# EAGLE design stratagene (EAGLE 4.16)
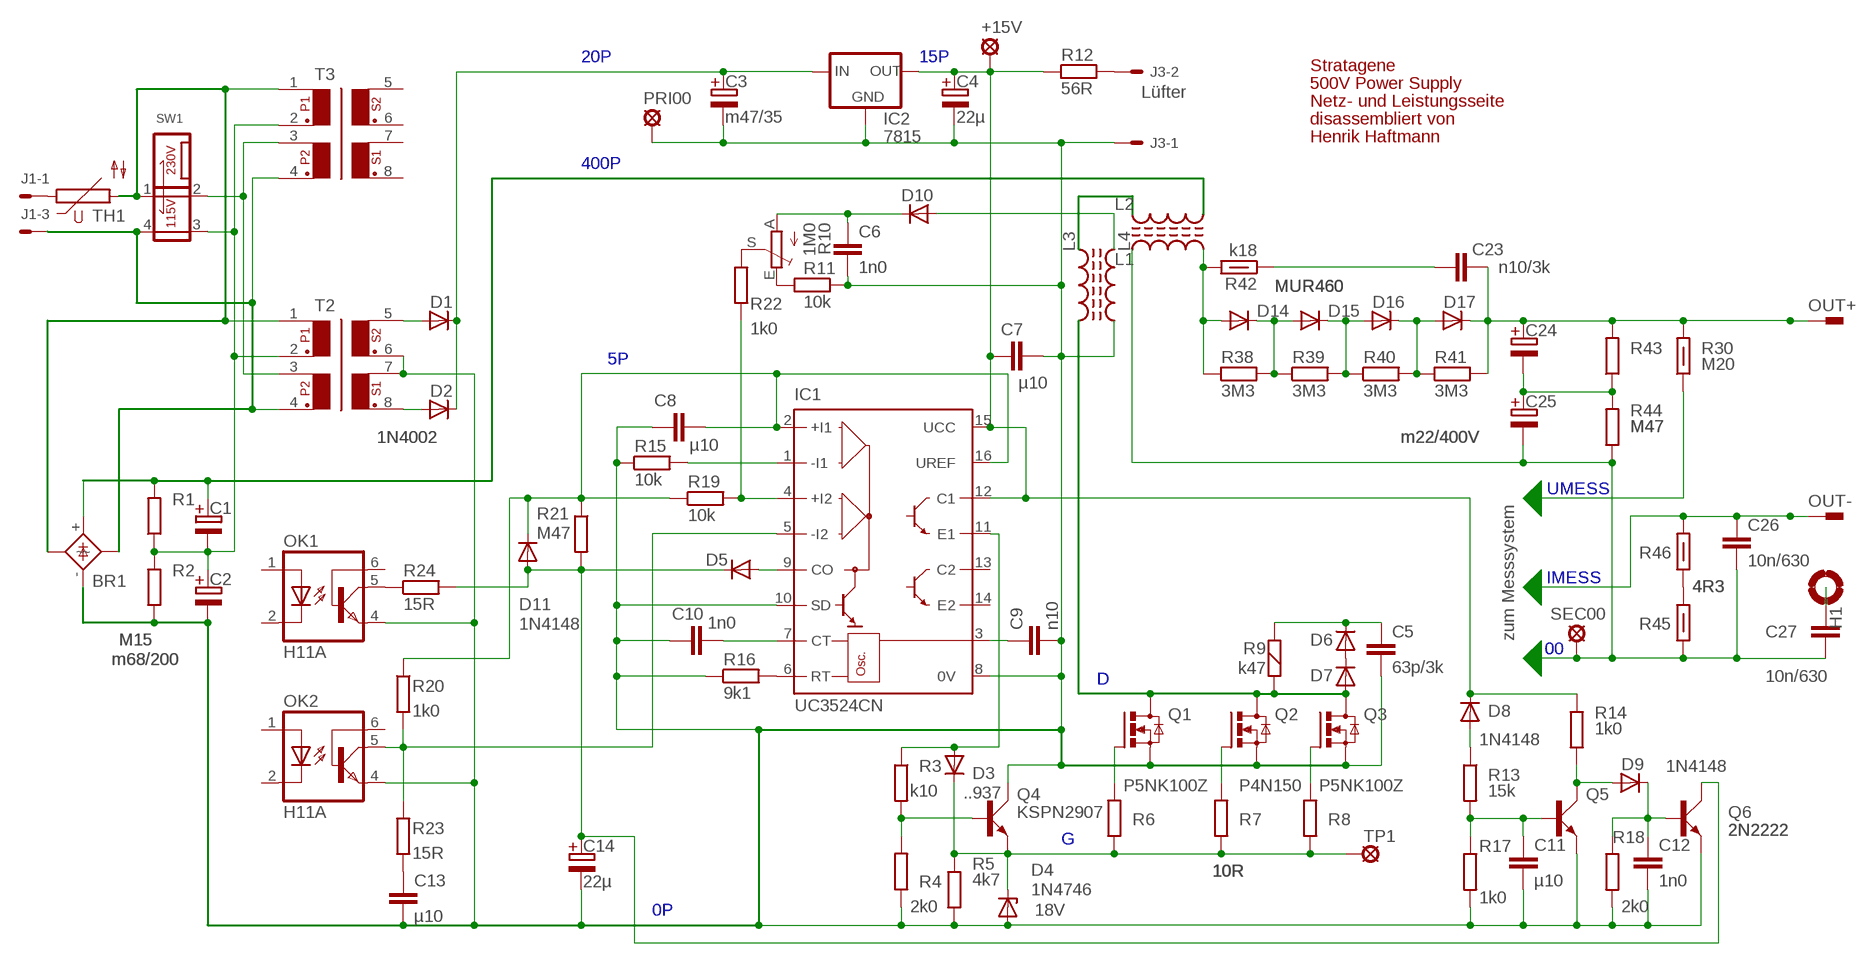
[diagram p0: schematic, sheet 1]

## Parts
+15V  LSP10  [LSP10]
BR1  DB  [GBPC1]
C1  m68/200  E04-26  [E04-26]
C2  m68/200  E04-26  [E04-26]
C3  m47/35  E02-10  [E02-10]
C4  22µ  E01-5  [E01-5]
C5  63p/3k  C02  [C02]
C6  1n0  C02  [C02]
C7  µ10  C02  [C02]
C8  µ10  C02  [C02]
C9  n10  C02  [C02]
C10  1n0  C02  [C02]
C11  µ10  C02  [C02]
C12  1n0  C02  [C02]
C13  µ10  C02  [C02]
C14  22µ  E01-5  [E01-5]
C23  n10/3k  C02  [C02]
C24  m22/400V  E04-26  [E04-26]
C25  m22/400V  E04-26  [E04-26]
C26  10n/630  C04  [C04]
C27  10n/630  C04  [C04]
D1  1N4002  D05  [D05]
D2  1N4002  D05  [D05]
D3  ..937  D05  [D05]
D4  1N4746  DZ05  [D05]
D5  D05  [D05]
D6  D05  [D05]
D7  D05  [D05]
D8  1N4148  D05  [D05]
D9  1N4148  D05  [D05]
D10  D05  [D05]
D11  1N4148  D05  [D05]
D14  MUR460  D07  [D07]
D15  MUR460  D07  [D07]
D16  MUR460  D07  [D07]
D17  MUR460  D07  [D07]
H1  MOUNT-PAD-ROUND4.1  [4,1-PAD]
IC1  UC3524CN  [DIL16]
IC2  7815  78XXS  [78XXS]
J1  22-27-2031-03  [6410-03]
J3  22-27-2021-02  [6410-02]
L1  L02  [R02]
L2  L04  [R04]
L3  L05  [R05]
L4  L05  [R05]
OK1  H11A  CNY17  [DIL06]
OK2  H11A  CNY17  [DIL06]
OUT+  PIN2F061.040  [F061.040]
OUT-  PIN2F061.040  [F061.040]
PRI00  LSP10  [LSP10]
Q1  P5NK100Z  NMOS220  [TO220V]
Q2  P4N150  NMOS220  [TO220V]
Q3  P5NK100Z  NMOS220  [TO220V]
Q4  KSPN2907  NPN92EBC  [TO92V]
Q5  2N2222  NPN92EBC  [TO92V]
Q6  2N2222  NPN92EBC  [TO92V]
R1  M15  R06  [R06]
R2  M15  R06  [R06]
R3  k10  R05  [R05]
R4  2k0  R05  [R05]
R5  4k7  R05  [R05]
R6  10R  R05  [R05]
R7  10R  R05  [R05]
R8  10R  R05  [R05]
R9  k47  R208  [R208]
R10  1M0  RAS64W  [S64W]
R11  10k  R05  [R05]
R12  56R  R05  [R05]
R13  15k  R05  [R05]
R14  1k0  R05  [R05]
R15  10k  R05  [R05]
R16  9k1  R05  [R05]
R17  1k0  R05  [R05]
R18  2k0  R05  [R05]
R19  10k  R05  [R05]
R20  1k0  R05  [R05]
R21  M47  R05  [R05]
R22  1k0  R05  [R05]
R23  15R  R05  [R05]
R24  15R  R05  [R05]
R30  M20  R08  [R08]
R38  3M3  R06  [R06]
R39  3M3  R06  [R06]
R40  3M3  R06  [R06]
R41  3M3  R06  [R06]
R42  k18  R08  [R08]
R43  M47  R06  [R06]
R44  M47  R06  [R06]
R45  4R3  R08  [R08]
R46  4R3  R08  [R08]
SEC00  LSP10  [LSP10]
SW1  SWA  [SWA]
T2  T2-2  [T42X34]
T3  T2-2  [T42X34]
TH1  P592  [P592]
TP1  LSP10  [LSP10]

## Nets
00: C25.- C26.2 C27.2 L1.1 R44.1 R45.1 SEC00.MP
0P: BR1.- C2.- C3.- C4.- C5.2 C6.2 C7.2 C8.2 C9.2 C10.2 C11.1 C12.2 C13.2 C14.- D4.1(A) IC1.8(0V) IC1.10(SD) IC2.GND J3.1 L4.2 OK1.4(EMI) OK2.4(EMI) PRI00.MP Q1.3(S) Q2.3(S) Q3.3(S) Q4.3(C) Q5.1(E) Q6.1(E) R2.1 R4.1 R5.2 R11.1 R15.1 R16.1 R17.2 R18.2 T2.6 T2.7
5P: C8.1 D11.2(K) IC1.2(+I1) IC1.16(UREF) R19.1 R20.1 R21.1
15P: +15V.MP C4.+ C7.1 D8.2(K) IC1.12(C1) IC1.15(UCC) IC2.OUT R12.1 R14.1
20P: C3.+ D1.2(K) D2.2(K) IC2.IN
400P: BR1.+ C1.+ L2.2 R1.2
D: D7.1(A) L3.2 Q1.2(D) Q2.2(D) Q3.2(D) R9.1
G: D3.2(K) D4.2(K) Q4.1(E) R5.1 R6.1 R7.1 R8.1 TP1.MP
IMESS: C26.1 OUT-.A1 OUT-.A2(1.1) R46.2
N$1: IC1.1(-I1) R15.2
N$2: C11.2 Q5.2(B) R13.2 R17.1
N$3: IC1.4(+I2) R19.2 R22.2
N$4: C14.+ D5.2(K) D11.1(A) Q6.3(C) R21.2 R24.2
N$5: J1.1 TH1.1
N$6: D14.1(A) L1.2 R38.1 R42.2
N$7: L2.1 L3.1
N$8: C23.1 R42.1
N$9: D14.2(K) D15.1(A) R38.2 R39.1
N$10: R45.2 R46.1
N$11: C24.- C25.+ R43.1 R44.2
N$14: D15.2(K) D16.1(A) R39.2 R40.1
N$15: D16.2(K) D17.1(A) R40.2 R41.1
N$16: C23.2 C24.+ D17.2(K) OUT+.A1 OUT+.A2(1.1) R30.2 R41.2 R43.2
N$19: Q1.1(G) R6.2
N$20: Q2.1(G) R7.2
N$21: Q3.1(G) R8.2
N$24: D5.1(A) IC1.9(CO)
N$25: C5.1 D6.2(K) R9.2
N$26: D6.1(A) D7.2(K)
N$27: J3.2 R12.2
N$28: D1.1(A) T2.5
N$29: D2.1(A) T2.8
N$30: C9.1 IC1.3(OSCOUT)
N$31: C10.1 IC1.7(CT)
N$32: Q4.2(B) R3.2 R4.2
N$34: D3.1(A) IC1.11(E1) R3.1
N$35: C27.1 H1.B4,1(MOUNT)
N$37: IC1.6(RT) R16.2
N$38: BR1.~@2(~) SW1.1 T2.1 T3.1 TH1.2
N$39: C1.- C2.+ R1.1 R2.2 SW1.3 T2.2 T3.2
N$40: SW1.2 T2.3 T3.3
N$41: BR1.~@1(~) J1.3 SW1.4 T2.4 T3.4
N$42: IC1.5(-I2) OK2.5(COL) R20.2 R23.1
N$44: D9.1(A) Q5.3(C) R14.2
N$45: D8.1(A) R13.1
N$46: D10.1(A) L4.1
N$47: C6.1 D10.2(K) R10.A
N$48: R10.S R22.1
N$49: R10.E R11.2
N$50: C12.1 D9.2(K) Q6.2(B) R18.1
N$51: OK1.5(COL) R24.1
N$52: C13.1 R23.2
UMESS: R30.1
Unconnected: IC1.13(C2) IC1.14(E2) J1.2 OK1.1(A) OK1.2(C) OK1.6(BAS) OK2.1(A) OK2.2(C) OK2.6(BAS) T3.5 T3.6 T3.7 T3.8

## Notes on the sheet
- Stratagene
- 500V Power Supply
- Lüfter
- Netz- und Leistungsseite
- disassembliert von
- Henrik Haftmann
- zum Messsystem
- 18V

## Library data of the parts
+15V PRI00 SEC00 TP1 = solpad:LSP10: SOLDER PAD
BR1 = stratagene:DB: Gleichrichterbrücke
C1-C4 C14 C24 C25 = stratagene:E: Elektrolytkondensator, gepolt
C5-C13 C23 C26 C27 = stratagene:C: Kondensator
D1-D3 D5-D11 D14-D17 = stratagene:D: Diode
D4 = stratagene:DZ: Z-Diode
H1 = holes:MOUNT-PAD-ROUND: MOUNTING PAD, round
IC1 = stratagene:UC3524: SWITCHMODE Pulse Width Modulation Control Circuit NCV494B http://onsemi.com tl494-d.pdf
IC2 = v-reg:78XXS: VOLTAGE REGULATOR
J1 = con-molex:22-?-03: CONNECTOR wire to board 2.54 mm (.1 inch) pitch header
J3 = con-molex:22-?-02: CONNECTOR
L1-L4 = stratagene:L: Spule, Drossel
OK1 OK2 = optocoupler:CNY17: SIEMENS OPTO COUPLER
OUT+ OUT- = con-faston:PIN2: Flachstecker Typ tyco/Electronics/AMP
Q1-Q3 = stratagene:NMOS: n-Kanal-MOSFET mit Bulkdiode
Q4-Q6 = stratagene:NPN: npn-Transistor Anschlussfolge CEB nur für SF225, SF240, SF245! Anschlussfolge ECB für japanische 2SC945 und ähnliche Anschlussfolge BEC für alle SMD-Transistoren
R1-R9 R11-R24 R30 R38-R46 = stratagene:R: Widerstand
R10 = stratagene:RA: Einstellpotenziometer dreipolig
SW1 = stratagene:SWA: Spannungsumschalter für Trafo Auch für Schaltnetzteile
T2 T3 = stratagene:T2-2: Netztrafo
TH1 = varistor:P592: VARISTOR

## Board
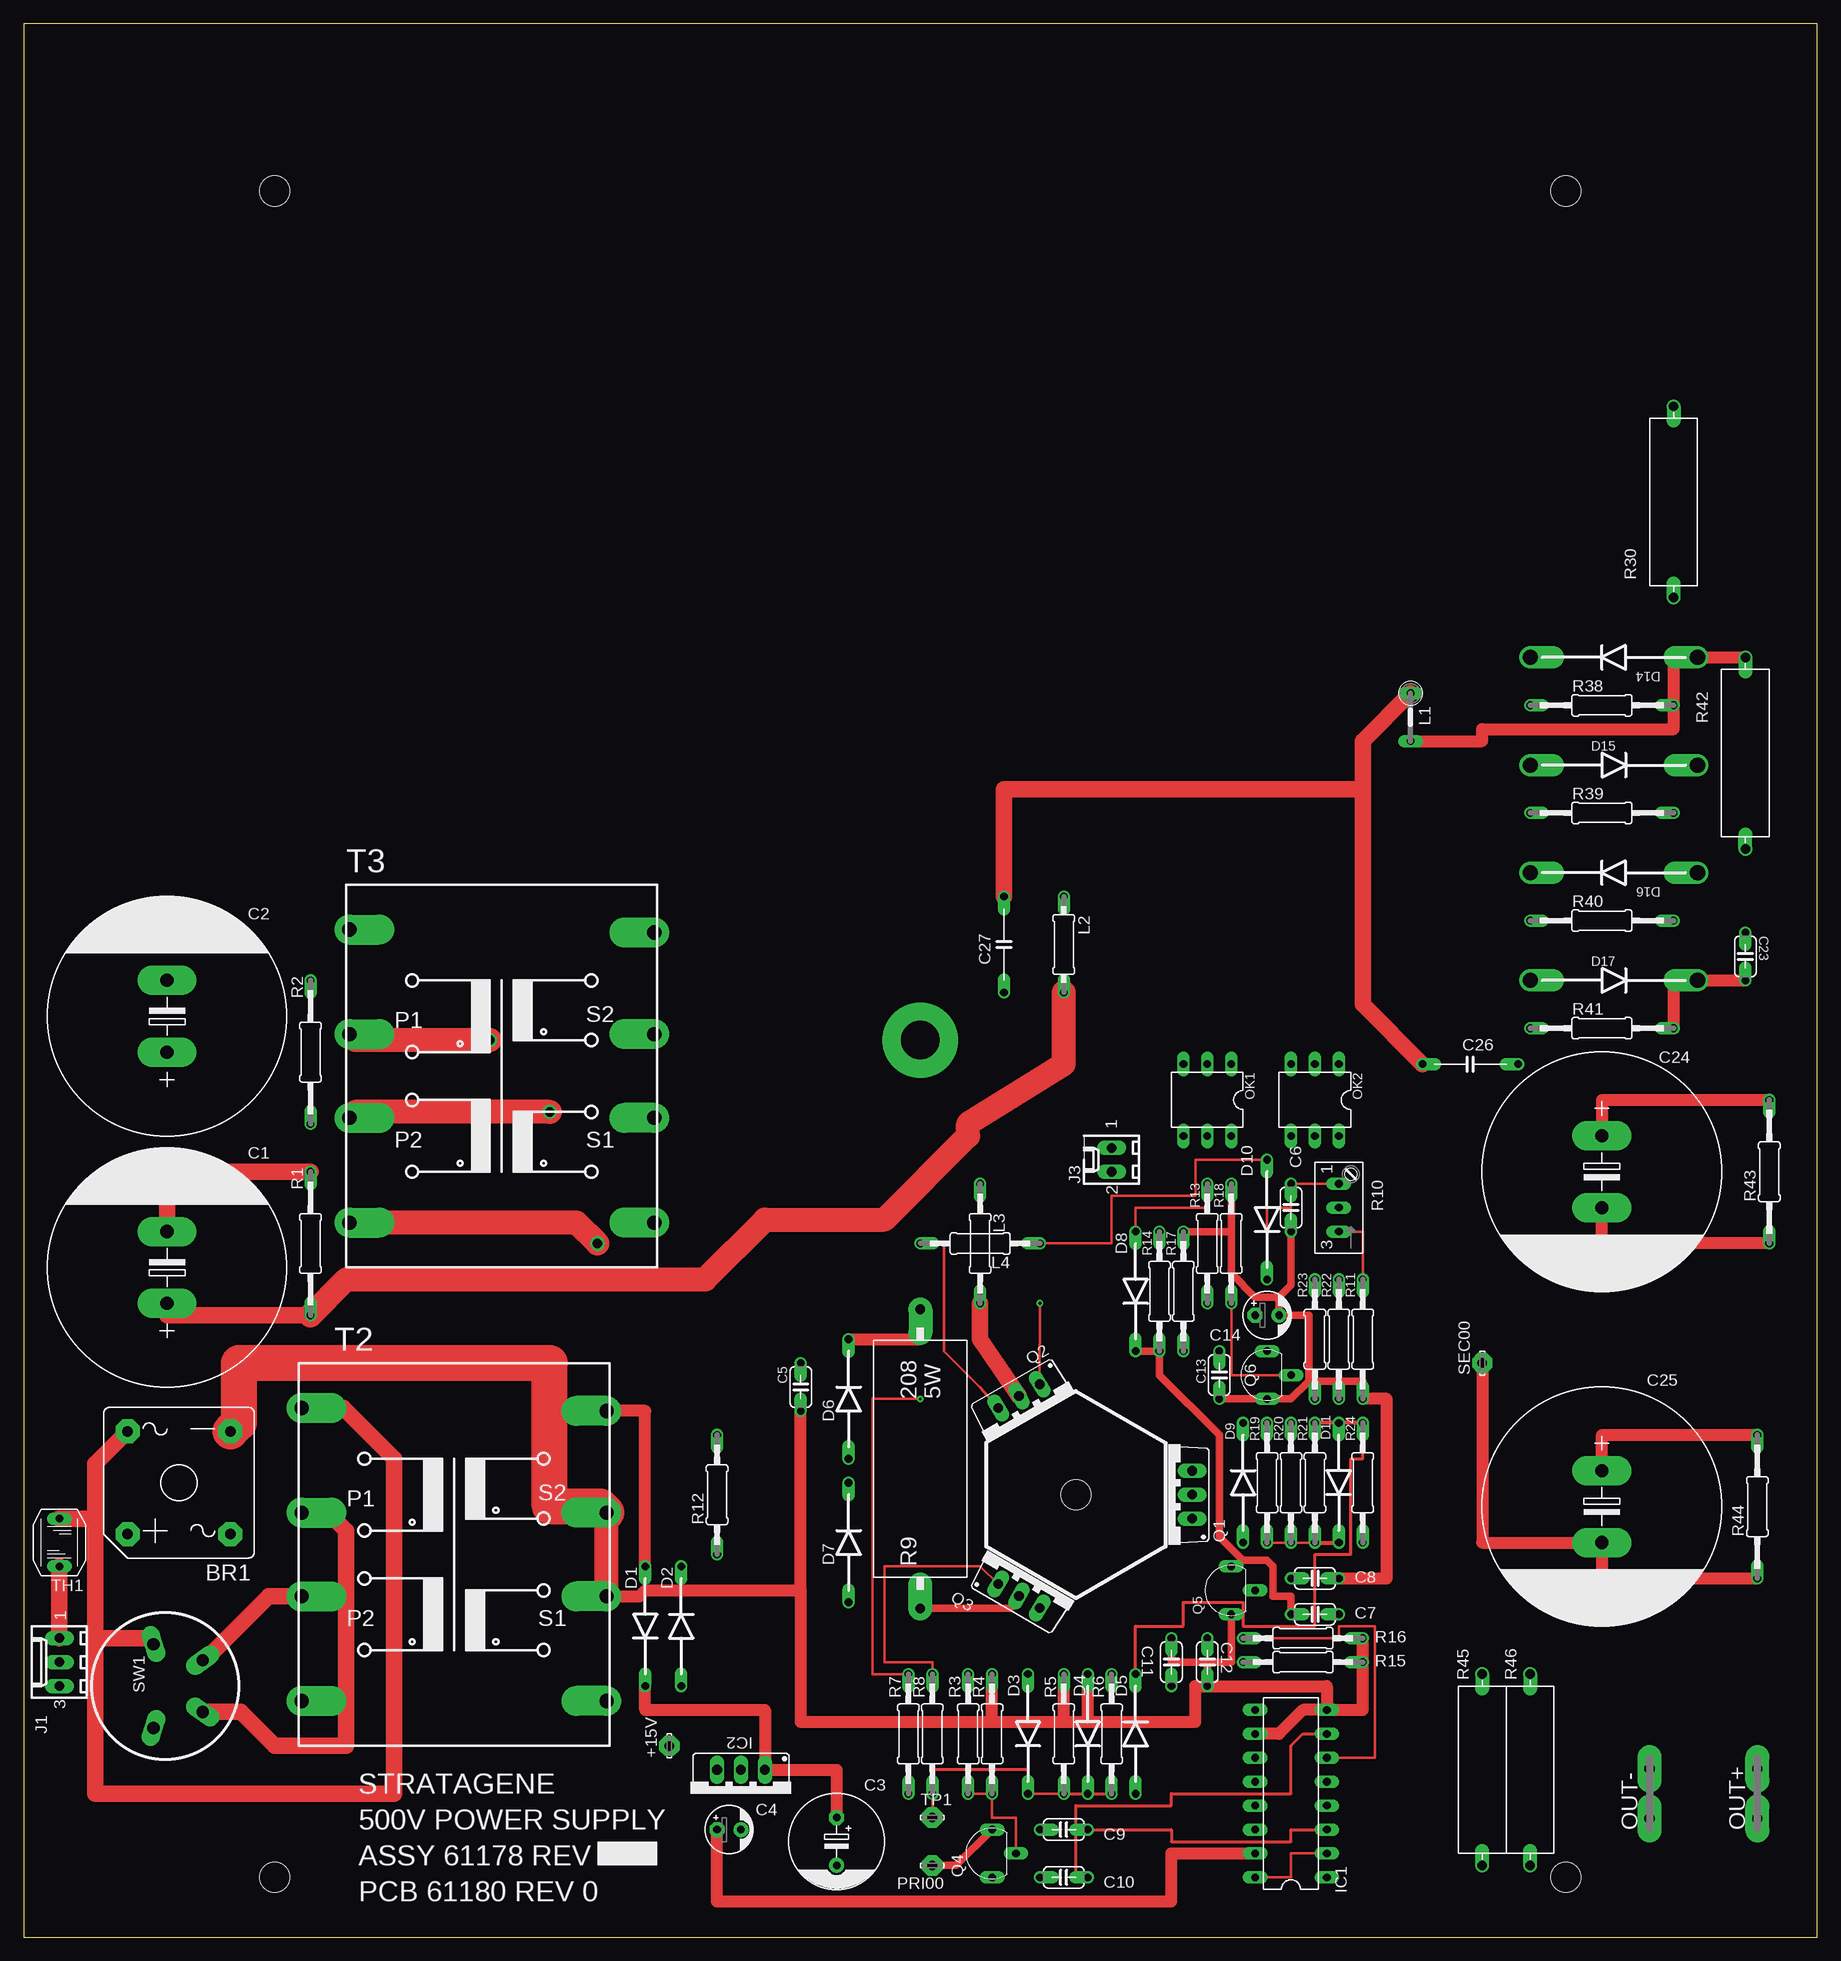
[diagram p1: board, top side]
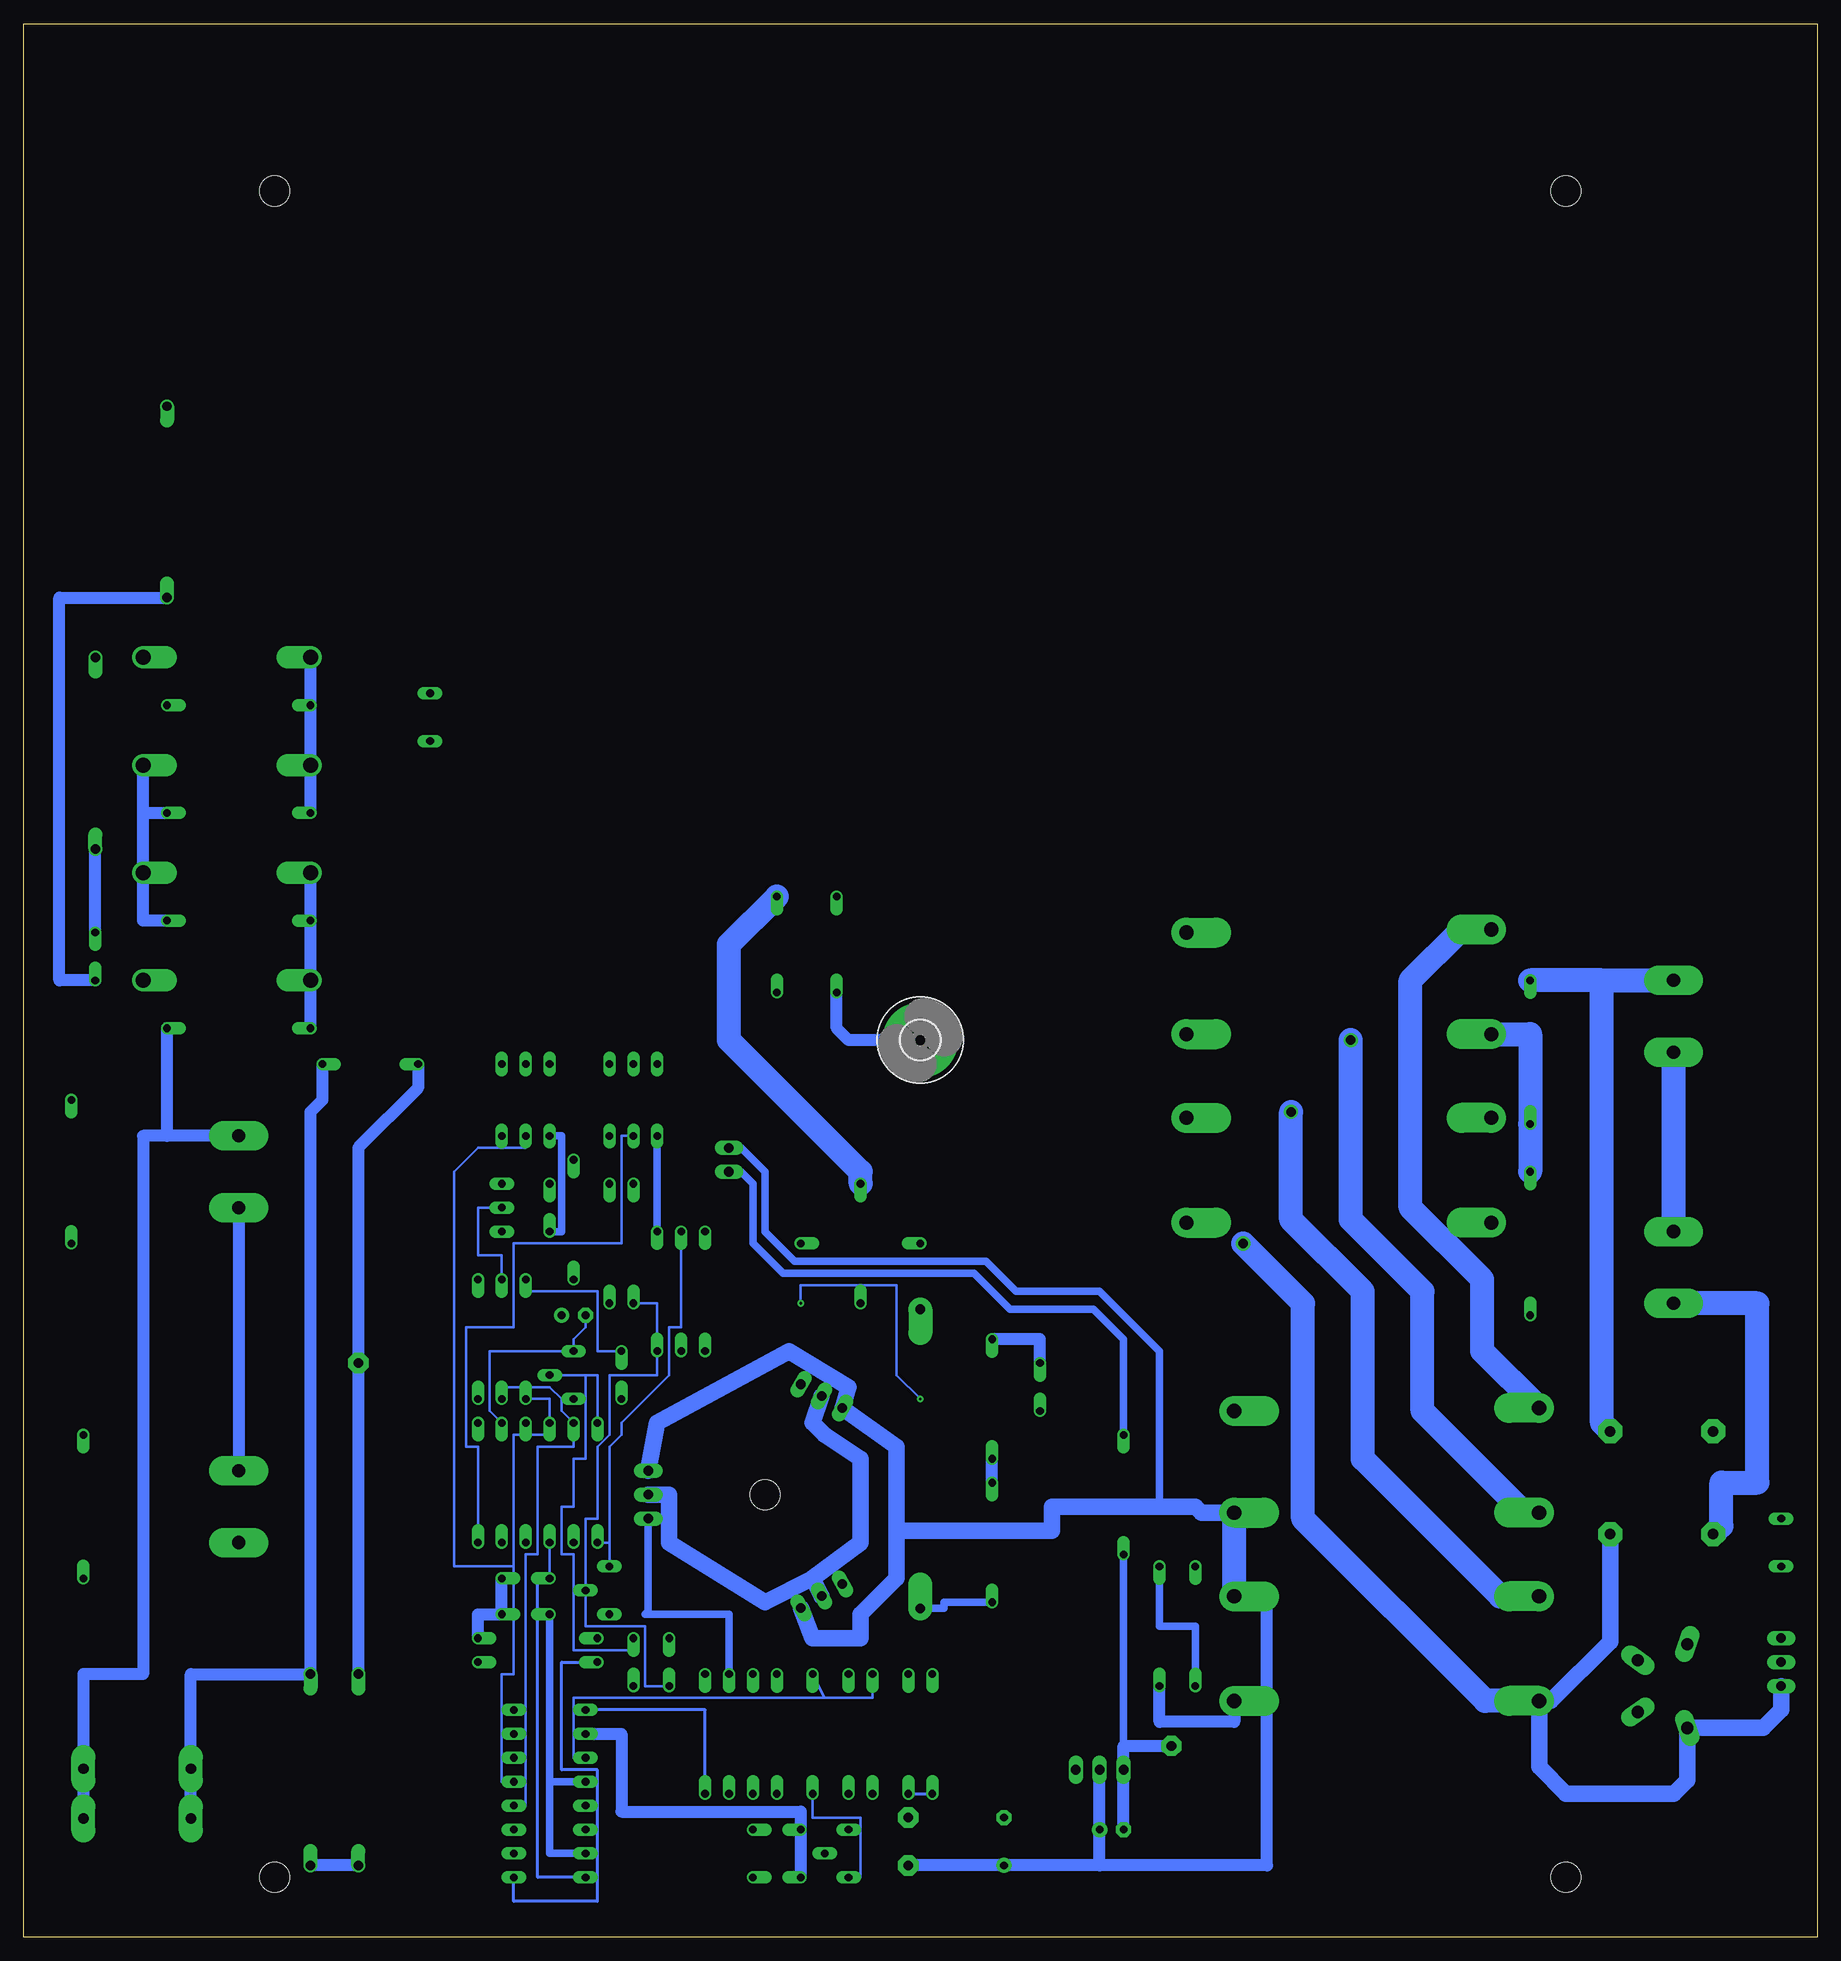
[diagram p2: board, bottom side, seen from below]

Size 190.5 x 203.2 mm. Coordinates in mm from the lower left corner, seen from the top.
Outline: 0,0 190.5,0 190.5,203.2 0,203.2 0,0
Copper layers (1+16): Top 0.035mm / dielectric 1.5mm / Bottom 0.035mm
Design rules "default": minimum track width 0.15mm, minimum drill 0.3mm, track to track 8mil, track to pad 8mil, pad to pad 8mil, via to via 8mil, smd to smd 8mil, copper to edge 40mil, drill to drill 8mil, minimum pad ring 10mil, minimum via ring 8mil, stop-mask expansion 4mil, vias tented up to drill 0mil, thermal gap 10mil
Holes 3.2 mm at 111.76,46.99 26.67,6.35 163.83,6.35 163.83,185.42 26.67,185.42

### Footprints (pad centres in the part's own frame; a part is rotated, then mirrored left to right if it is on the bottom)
LSP10 = drill 1.016 pad 2.159 octagon: MP 0,0
GBPC1 = drill 1.118 pad 2.54 octagon: + 5.461,5.461; - -5.461,-5.461; ~@1 -5.461,5.461; ~@2 5.461,-5.461
E04-26 = drill 1.4 pad 3.15 long: + 0,3.81; - 0,-3.81
E02-10 = drill 0.813 pad 1.6 octagon: + 0,2.54 | drill 0.813 pad 1.6 round: - 0,-2.54
E01-5 = drill 0.813 pad 1.6 octagon: + 0,1.27 | drill 0.813 pad 1.6 round: - 0,-1.27
C02 = drill 0.813 offset: 1 -2.54,0; 2 2.54,0
C04 = drill 0.813 offset: 1 -5.08,0; 2 5.08,0
D05 = drill 0.813 offset: 1 -6.35,0; 2 6.35,0
D07 = drill 1.6 offset: 1 -8.89,0; 2 8.89,0
4,1-PAD = drill 4.1 pad 8 round: B4,1 0,0
DIL16 = drill 0.813 long: 1 -8.89,-3.81; 2 -6.35,-3.81; 3 -3.81,-3.81; 4 -1.27,-3.81; 5 1.27,-3.81; 6 3.81,-3.81; 7 6.35,-3.81; 8 8.89,-3.81; 9 8.89,3.81; 10 6.35,3.81; 11 3.81,3.81; 12 1.27,3.81; 13 -1.27,3.81; 14 -3.81,3.81; 15 -6.35,3.81; 16 -8.89,3.81
78XXS = drill 1.016 long: GND 0,-2.54; IN -2.54,-2.54; OUT 2.54,-2.54
6410-03 = drill 1.016 long: 1 2.54,0; 2 0,0; 3 -2.54,0
6410-02 = drill 1.016 long: 1 1.27,0; 2 -1.27,0
R02 = drill 0.813 long: 1 -2.54,0; 2 2.54,0
R04 = drill 0.813 offset: 1 -5.08,0; 2 5.08,0
R05 = drill 0.813 offset: 1 -6.35,0; 2 6.35,0
DIL06 = drill 0.813 long: 1 -2.54,-3.81; 2 0,-3.81; 3 2.54,-3.81; 4 2.54,3.81; 5 0,3.81; 6 -2.54,3.81
F061.040 = drill 1.1 pad 2.54 long: A1 -2.65,0; A2 2.65,0
TO220V = drill 1.016 long: 1 -2.54,-2.54; 2 0,-2.54; 3 2.54,-2.54
TO92V = drill 0.813 long: 1 -2.54,0; 2 0,-2.54; 3 2.54,0
R06 = drill 0.813 offset: 1 -7.62,0; 2 7.62,0
R208 = drill 1.016 pad 2.54 offset: 1 -15.875,0; 2 15.875,0
S64W = drill 0.813 long: A 2.54,1.27; E -2.54,1.27; S 0,1.27
R08 = drill 1 offset: 1 -10.16,0; 2 10.16,0
SWA = drill 1.3 long: 1 -4.45,-1.45; 2 -2.75,3.8; 3 2.75,3.8; 4 4.45,-1.45
T42X34 = drill 1.5 pad 3.175 offset: 1 -16.192,15.557; 2 -16.192,4.445; 3 -16.192,-4.445; 4 -16.192,-15.557; 5 16.192,15.24; 6 16.192,4.445; 7 16.192,-4.445; 8 16.192,-15.557
P592 = drill 0.813 long: 1 0,2.54; 2 0,-2.54

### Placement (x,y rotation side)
+15V  68.58,20.32 90 top
BR1  16.51,48.26 180 top
C1  15.24,71.12 180 top
C2  15.24,97.79 180 top
C3  86.36,10.16 0 top
C4  74.93,11.43 90 top
C5  82.55,58.42 270 top
C6  134.62,77.47 270 top
C7  137.16,34.29 0 top
C8  137.16,38.1 0 top
C9  110.49,11.43 180 top
C10  110.49,6.35 180 top
C11  121.92,29.21 270 top
C12  125.73,29.21 270 top
C13  127,59.69 270 top
C14  132.08,66.04 90 top
C23  182.88,104.14 270 top
C24  167.64,81.28 0 top
C25  167.64,45.72 0 top
C26  153.67,92.71 180 top
C27  104.14,105.41 90 top
D1  66.04,33.02 270 top
D2  69.85,33.02 90 top
D3  106.68,21.59 270 top
D4  113.03,21.59 270 top
D5  118.11,21.59 90 top
D6  87.63,57.15 90 top
D7  87.63,41.91 90 top
D8  118.11,68.58 270 top
D9  129.54,48.26 90 top
D10  132.08,76.2 270 top
D11  139.7,48.26 270 top
D14  168.91,135.89 180 top
D15  168.91,124.46 0 top
D16  168.91,113.03 180 top
D17  168.91,101.6 0 top
H1  95.25,95.25 0 bottom
IC1  134.62,15.24 90 top
IC2  76.2,15.24 180 top
J1  3.81,29.21 90 top
J3  115.57,82.55 90 top
L1  147.32,129.54 270 top
L2  110.49,105.41 270 top
L3  101.6,73.66 270 top
L4  101.6,73.66 180 top
OK1  125.73,88.9 180 top
OK2  137.16,88.9 180 top
OUT+  184.15,15.24 90 top
OUT-  172.72,15.24 90 top
PRI00  96.52,7.62 180 top
Q1  121.6,46.99 90 top
Q2  107,55.24 210 top
Q3  107,38.42 330 top
Q4  102.87,8.89 90 top
Q5  128.27,36.83 90 top
Q6  132.08,59.69 90 top
R1  30.48,73.66 270 top
R2  30.48,93.98 270 top
R3  100.33,21.59 270 top
R4  102.87,21.59 270 top
R5  110.49,21.59 90 top
R6  115.57,21.59 90 top
R7  93.98,21.59 90 top
R8  96.52,21.59 90 top
R9  95.25,50.8 90 top
R10  140.97,77.47 90 top
R11  142.24,63.5 90 top
R12  73.66,46.99 90 top
R13  125.73,73.66 270 top
R14  120.65,68.58 90 top
R15  135.89,29.21 180 top
R16  135.89,31.75 180 top
R17  123.19,68.58 90 top
R18  128.27,73.66 90 top
R19  132.08,48.26 90 top
R20  134.62,48.26 90 top
R21  137.16,48.26 90 top
R22  139.7,63.5 270 top
R23  137.16,63.5 90 top
R24  142.24,48.26 90 top
R30  175.26,152.4 270 top
R38  167.64,130.81 180 top
R39  167.64,119.38 0 top
R40  167.64,107.95 180 top
R41  167.64,96.52 0 top
R42  182.88,125.73 90 top
R43  185.42,81.28 90 top
R44  184.15,45.72 90 top
R45  154.94,17.78 270 top
R46  160.02,17.78 90 top
SEC00  154.94,60.96 90 top
SW1  15.24,26.67 270 top
T2  45.72,40.64 0 top
T3  50.8,91.44 0 top
TH1  3.81,41.91 180 top
TP1  96.52,12.7 0 top
U$1  [KK]  111.76,46.99 0 top

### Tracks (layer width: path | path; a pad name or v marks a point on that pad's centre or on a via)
00
  Top 1.27: R44.1 167.64,38.1 C25.- 154.94,41.91 SEC00.MP
  Top 1.778: L1.1 142.24,127 142.24,121.92 | C26.2 142.24,99.06 142.24,121.92 | C27.2 104.14,121.92 142.24,121.92
  Bottom 1.27: R45.1 SEC00.MP 154.94,83.82 148.59,90.17 C26.2
0P
  Top 0.254: L4.2 97.79,73.66 97.79,62.23 101.6,58.42 Q2.3
  Top 0.813: Q4.3 99.06,7.62 PRI00.MP | Q5.1 128.27,29.21 125.73,29.21 | 125.73,29.21 121.92,29.21 C11.1 | C12.2 125.73,29.21 | C6.2 134.62,69.22 133.35,67.94 | 133.35,67.94 130.81,67.94 128.27,70.48 128.27,74.93 | 128.27,74.93 R18.2 | 133.35,67.94 C14.- 136.53,66.04 136.53,59.05 | 128.27,74.93 R17.2 | C13.2 Q6.1 134.62,57.15 136.53,59.05 | 136.53,59.05 142.24,59.05 R11.1
  Top 1.27: R11.1 144.78,57.15 144.78,38.1 C8.2 | R16.1 R15.1 142.24,24.13 IC1.8 | IC1.8 138.43,26.67 C12.2 124.46,26.67 124.46,22.86 113.03,22.86 | 82.55,36.83 C5.2 | 82.55,36.83 66.04,36.83 65.41,36.2 T2.7 | 102.87,22.86 R4.1 | 102.87,22.86 82.55,22.86 82.55,36.83 | 110.49,22.86 R5.2 | 102.87,22.86 110.49,22.86 | 113.03,22.86 D4.1 | 110.49,22.86 113.03,22.86 | IC1.8 135.89,24.13 133.35,21.59 IC1.10
  Top 2.54: T2.7 T2.6
  Top 3.81: BR1.- 22.86,54.61 22.86,60.96 55.88,60.96 55.88,45.72 61.28,45.72 T2.6
  Bottom 0.813: J3.1 114.3,83.82 111.76,81.28 111.76,74.93 108.58,71.75 88.27,71.75 85.09,68.58 76.2,68.58 69.85,62.23 69.85,45.72 | OK2.4 133.35,85.09 133.35,74.93 C6.2 | R17.2 OK1.4
  Bottom 1.27: C8.2 C7.2 142.24,34.29 R16.1 | C10.2 C9.2 107.95,13.34 127,13.34 127,21.59 IC1.10 | IC2.GND C4.- 76.2,7.62 | 76.2,7.62 58.42,7.62 58.42,36.2 T2.7 | 76.2,7.62 C3.- PRI00.MP
  Bottom 1.778: T2.6 65.41,45.09 66.04,45.72 69.85,45.72 81.28,45.72 81.28,43.18 97.79,43.18 | 97.79,43.18 97.79,52.07 Q2.3 102.87,58.42 109.22,62.23 123.19,54.61 Q1.3 | Q3.3 106.68,31.75 101.6,31.75 101.6,34.29 97.79,38.1 97.79,43.18
  Bottom 2.54: T2.7 T2.6 | 22.86,101.6 C2.- | 22.86,101.6 R2.1 | BR1.- 22.86,54.61 22.86,101.6
5P
  Top 0.254: IC1.2 134.62,8.89 134.62,6.35 IC1.16 | R19.1 R20.1 R21.1
  Top 0.406: R21.1 D11.2
  Bottom 0.254: C8.1 R20.1
  Bottom 0.305: IC1.16 135.89,6.35 135.89,38.1 C8.1
15P
  Top 0.813: D8.2 R14.1 120.65,59.69 127,53.34 127,42.55 129.54,40.01 132.08,40.01 132.72,39.37 132.72,36.2 134.62,36.2 C7.1
  Top 1.27: IC1.15 121.92,8.89 121.92,3.81 73.66,3.81 C4.+
  Bottom 0.813: 73.66,20.32 R12.1 | 134.62,16.51 IC1.12 | 134.62,16.51 134.62,8.89 IC1.15 | 134.62,16.51 C7.1
  Bottom 1.27: C4.+ IC2.OUT 73.66,20.32 +15V.MP
20P
  Top 1.27: C3.+ 86.36,17.78 IC2.IN 78.74,24.13 66.04,24.13 D1.2
  Bottom 0.813: D2.2 69.85,33.02 66.04,33.02 D1.2
400P
  Top 1.778: R1.2 15.24,66.04 C1.+
  Top 2.54: R1.2 34.29,69.85 72.39,69.85 78.74,76.2 91.44,76.2 100.33,85.09 100.33,86.36 110.49,92.71 L2.2
  Bottom 2.54: BR1.+ 10.16,43.69 10.16,48.26 6.35,48.26 6.35,67.31 C1.+
D
  Top 0.813: R9.1 104.78,34.92 105.41,35.56 Q3.2
  Top 1.778: Q2.2 101.6,63.5 L3.2
  Bottom 0.813: D7.1 92.71,35.56 92.71,34.92 R9.1
  Bottom 1.778: Q1.2 121.92,46.99 121.92,41.91 111.76,35.56 106.68,38.1 | Q3.2 106.68,38.1 | Q2.2 106.68,54.61 105.41,53.34 101.6,50.8 101.6,41.91 106.68,38.1
G
  Top 0.254: R5.1 D3.2 106.68,17.78
  Top 0.305: TP1.MP R8.1 96.52,17.78 106.68,17.78 | R5.1 D4.2 R6.1
  Bottom 0.254: Q4.1 101.6,6.35 101.6,12.7 106.68,12.7 D3.2
  Bottom 0.305: R8.1 R7.1
IMESS
  Bottom 1.27: OUT-.A1 172.72,17.78 | 172.72,17.78 OUT-.A2 | 172.72,17.78 172.72,27.94 R46.2 160.02,87.63 158.75,88.9 C26.1
N$1
  Bottom 0.305: IC1.1 138.43,3.81 129.54,3.81 129.54,17.78 133.35,17.78 133.35,29.21 R15.2
N$2
  Bottom 0.254: R13.2 123.19,67.31 R17.1 123.19,59.69 128.27,59.69 128.27,53.34 129.54,52.07 129.54,44.45 130.81,44.45 Q5.2 130.81,33.02 124.46,33.02 124.46,26.67 C11.2
N$3
  Bottom 0.254: IC1.4 137.16,13.97 137.16,40.64 135.89,40.64 135.89,52.07 132.08,52.07 R19.2 133.35,55.88 133.35,57.15 134.62,58.42 139.7,58.42 R22.2
N$4
  Top 0.305: D5.2 118.11,33.02 123.19,33.02 123.19,35.56 129.54,35.56 129.54,33.02 137.16,33.02 137.16,40.64 140.97,40.64 140.97,50.8 142.24,50.8 R24.2
  Top 0.406: R21.2 D11.1 R24.2
  Bottom 0.254: C14.+ 130.81,64.77 132.08,63.5 Q6.3 140.97,62.23 140.97,55.88 D11.1
N$5
  Top 1.778: J1.1 TH1.1
N$6
  Top 1.27: L1.2 154.94,127 154.94,128.27 175.26,128.27 R38.1 175.26,135.89 D14.1 R42.2
N$7
  Bottom 2.54: L3.1 101.6,81.28 115.57,95.25 115.57,105.41 L2.1
N$8
  Bottom 1.27: C23.1 R42.1
N$9
  Bottom 1.27: D14.2 R38.2 D15.1 R39.1
N$10
  Bottom 1.27: R45.2 R46.1
N$11
  Top 1.27: R44.2 167.64,53.34 C25.+ | R43.1 167.64,73.66 C24.-
  Bottom 1.27: C24.- C25.+
N$14
  Bottom 1.27: 177.8,119.38 D16.1 177.8,107.95 R40.1 | 177.8,119.38 D15.2 | 177.8,119.38 R39.2
N$15
  Bottom 1.27: D16.2 R40.2 D17.1 R41.1
N$16
  Top 1.27: R41.2 175.26,101.6 D17.2 C23.2 | R43.2 167.64,88.9 C24.+
  Bottom 1.27: 175.26,85.09 R41.2 | C24.+ 175.26,85.09 | R30.2 186.69,142.24 186.69,101.6 C23.2 | 175.26,85.09 177.8,85.09 177.8,27.94 184.15,27.94 OUT+.A2 OUT+.A1
N$19
  Bottom 0.813: Q1.1 124.14,34.61 124.46,34.29 115.57,34.29 R6.2
N$20  (via drill 0.3)
  Top 0.254: R7.2 90.17,27.94 90.17,57.15 v95.25,57.15 | v107.95,67.31 Q2.1
  Bottom 0.254: v107.95,67.31 107.95,69.22 97.79,69.22 97.79,59.69 v95.25,57.15
N$21
  Top 0.254: R8.2 96.52,29.21 91.44,29.21 91.44,39.37 101.6,39.37 Q3.1
N$24
  Bottom 0.305: IC1.9 118.11,24.13 D5.1
N$25
  Top 1.27: R9.2 95.25,63.5 D6.2
  Bottom 1.27: D6.2 82.55,63.5 C5.1
N$26
  Bottom 1.27: D7.2 D6.1
N$27
  Bottom 0.813: J3.2 114.3,81.28 113.03,80.01 113.03,73.66 109.86,70.48 89.53,70.48 85.72,66.67 76.83,66.67 73.66,63.5 R12.2
N$28
  Top 1.27: T2.5 66.04,55.88 D1.1
N$29
  Bottom 1.27: T2.8 61.91,22.86 69.85,22.86 D2.1
N$30
  Top 0.305: C9.1 121.92,11.43 121.92,10.16 134.62,10.16 134.62,11.43 IC1.3
N$31
  Top 0.305: C10.1 111.76,6.35 111.76,13.97 121.92,13.97 121.92,15.24 134.62,15.24 134.62,20.32 135.89,21.59 IC1.7
N$32
  Top 0.254: R3.2 R4.2 102.87,12.7 105.41,12.7 Q4.2
N$34
  Bottom 0.254: R3.1 100.33,25.4 105.41,25.4 | 105.41,25.4 D3.1 | 105.41,25.4 132.08,25.4 132.08,19.05 IC1.11
N$35
  Bottom 1.27: H1.B4,1 102.87,95.25 104.14,96.52 C27.1
N$37
  Top 0.254: IC1.6 143.51,19.05 143.51,33.02 139.7,33.02 139.7,31.75 R16.2
N$38
  Top 1.778: T2.1 33.97,56.2 39.37,50.8 39.37,15.24 7.62,15.24 7.62,31.75 | 7.62,31.75 7.62,44.45 | SW1.1 13.16,31.75 7.62,31.75 | 7.62,44.45 TH1.2 | BR1.~@2 7.62,50.29 7.62,44.45
  Bottom 2.54: T3.1 37.78,107 43.18,101.6 43.18,77.47 35.56,69.85 35.56,62.23 T2.1
N$39  (via drill 1)
  Top 1.778: R1.1 15.24,81.28 C1.- | SW1.3 23.07,23.92 26.67,20.32 34.29,20.32 34.29,43.18 32.38,45.09 T2.2
  Top 2.54: T3.2 35.24,95.25 v49.53,95.25
  Bottom 2.54: T2.2 31.11,45.09 41.91,55.88 41.91,68.58 49.53,76.2 v49.53,95.25 | C1.- C2.+ | R1.1 R2.2 30.48,95.89 T3.2
N$40  (via drill 1)
  Top 1.778: SW1.2 19.26,29.42 26.04,36.2 T2.3
  Top 2.54: T3.3 35.24,87.63 v55.88,87.63
  Bottom 2.54: v55.88,87.63 55.88,76.2 48.26,68.58 48.26,50.8 33.66,36.2 T2.3
N$41  (via drill 1)
  Top 2.54: T3.4 58.74,75.88 v60.96,73.66
  Bottom 1.778: BR1.~@1 21.97,31.37 28.26,25.08 T2.4 29.53,18.1 26.67,15.24 15.24,15.24 13.79,16.69 SW1.4 5.72,22.22 3.81,24.13 J1.3
  Bottom 2.54: T2.4 35.24,25.08 54.61,44.45 54.61,67.31 v60.96,73.66
N$42
  Bottom 0.254: OK2.5 137.16,83.82 142.24,83.82 144.78,81.28 144.78,39.37 138.43,39.37 | 138.43,39.37 138.43,27.94 139.7,27.94 139.7,16.51 IC1.5 | 138.43,39.37 138.43,53.34 134.62,53.34 R20.2 134.62,57.15 R23.1
N$44
  Bottom 0.254: Q5.3 128.27,41.91 | 128.27,41.91 D9.1 | R14.2 120.65,64.77 121.92,64.77 121.92,59.69 127,54.61 127,53.34 128.27,52.07 128.27,41.91
N$45
  Top 0.254: D8.1 118.11,77.47 125.73,77.47 R13.1
N$46
  Top 0.254: L4.1 115.57,73.66 115.57,78.74 124.46,78.74 124.46,82.55 D10.1
N$47
  Top 0.254: D10.2 132.08,77.47 134.62,77.47 C6.1 R10.A
N$48
  Bottom 0.254: R10.S 142.24,77.47 142.24,72.39 139.7,72.39 R22.1
N$49
  Top 0.254: R10.E 142.24,74.93 R11.2
N$50
  Top 0.254: R18.1 128.27,59.69 Q6.2
  Bottom 0.254: 130.81,59.69 129.54,59.69 D9.2 | 130.81,59.69 Q6.2 | 130.81,59.69 130.81,50.8 132.08,50.8 132.08,45.72 133.35,45.72 133.35,40.64 132.08,40.64 132.08,30.48 125.73,30.48 C12.1
N$51
  Bottom 0.254: OK1.5 127,85.09 127,73.66 138.43,73.66 138.43,64.77 143.51,64.77 143.51,52.07 142.24,52.07 R24.1
N$52
  Bottom 0.254: R23.2 137.16,68.58 129.54,68.58 129.54,62.23 C13.1

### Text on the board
tPlace: STRATAGENE | 500V POWER SUPPLY | ASSY 61178 REV | PCB 61180 REV 0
